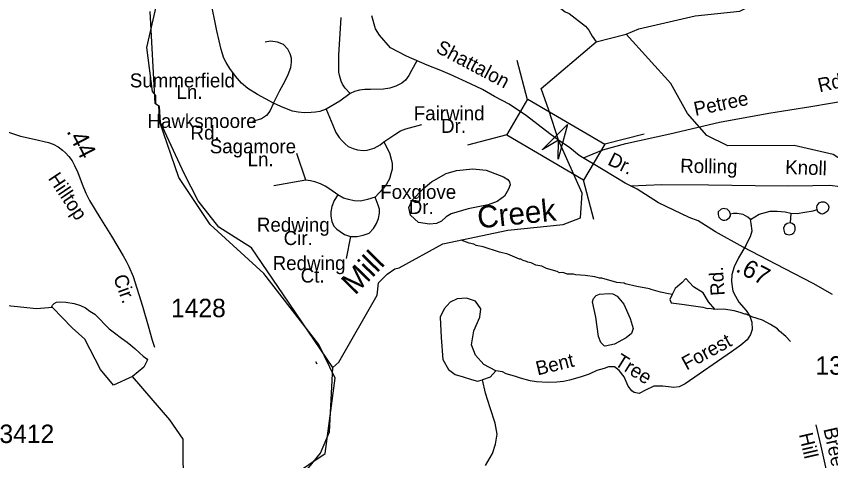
# Model space of a CAD drawing. Extents: x 1547597 to 1699558, y 810033 to 920809.
# Drawn here: x 1600633 to 1606161, y 866479 to 869495 of the extents above; entities that cross this region are included whole.
import ezdxf

# ---------------------------------------------------------------- set-up
doc = ezdxf.new("R2010")
doc.units = 0
for name, color, linetype in [('Exist Boundary Political City Limit New', 7, 'Continuous'), ('Exist Hydrographic Creek Single Shore', 7, 'Continuous'), ('Exist Hydrographic Creek Single Shore Label', 7, 'Continuous'), ('Exist Hydrographic Misc Water Feature', 7, 'Continuous'), ('Exist Road Non-System Type 51', 7, 'Continuous'), ('Exist Road Non-System Type 51 Label', 7, 'Continuous'), ('Exist Road Secondary Mileage Hundredths English Label', 7, 'Continuous'), ('Exist Road Secondary Structure Standard Bridge Attributed CELL', 7, 'Continuous'), ('Exist Road Secondary Structure Standard Bridge CELL', 7, 'Continuous'), ('Exist Road Secondary Type 51 Attributed', 7, 'Continuous'), ('Exist Road Secondary Type 51 Label', 7, 'Continuous'), ('Exist Road Secondary Type 51 Number Label', 7, 'Continuous'), ('Map Preparation Boundary City Limit Buffer Line', 7, 'Continuous')]:
    doc.layers.add(name, color=color, linetype=linetype)

msp = doc.modelspace()

# ---------------------------------------------------------------- linework, layer by layer
at = {"layer": 'Exist Boundary Political City Limit New'}
msp.add_lwpolyline([(1602182.3, 866158.9), (1602728.1, 866528.3), (1602797.7, 867040.1), (1602687, 867268.5), (1602313.6, 867748.7), (1601948.4, 868081.1), (1601736.8, 868400.2), (1601607.9, 868777), (1601600.8, 868885.5), (1601575.9, 868902.4), (1601540.5, 869526.8)], dxfattribs=at)
at = {"layer": 'Exist Hydrographic Creek Single Shore'}
for p, q in [((1602673.7, 867133.8), (1602666.3, 867149.1)), ((1602782, 867111.8), (1602822, 867147))]:
    msp.add_line(p, q, dxfattribs=at)
for points in [[(1602782, 867111.8), (1602446.7, 867604.6), (1602229.1, 867924.7), (1602006.9, 868065), (1601866.6, 868242.5), (1601771.4, 868427.8), (1601611.7, 868773.7), (1601604.6, 868882.2), (1601579.7, 868899.1), (1601580.6, 868958.2), (1601556.6, 868985), (1601518.7, 869284.4), (1601660.7, 869908.5), (1601652.7, 869984.2), (1601436.5, 870359), (1601193.2, 870745.3), (1601139.7, 870848.1), (1601187.9, 871530), (1601203.8, 872030.5)], [(1604772.6, 869373), (1604858.4, 869409.8), (1605241.6, 869498.8), (1605544.1, 869530.6), (1605598.7, 869556.2), (1605619.6, 869874.2), (1605773, 870044.1), (1605865.7, 870145), (1606007.7, 870168.4), (1606156.7, 870139), (1606380.7, 870062.2), (1606464.7, 870086.8), (1606526.7, 870384.3)], [(1602822, 867147), (1603081.4, 867603.2), (1603090.9, 867686.5), (1603150.5, 867745.3), (1603201.6, 867782.2), (1603230.9, 867786.9), (1603526.7, 867950.3), (1603969.7, 868043.1), (1604345.6, 868081.3), (1604462.6, 868128.3), (1604473.7, 868295.4), (1604312.8, 868655.6), (1604247.6, 868858.1), (1604194.2, 869006.1), (1604567.5, 869322.3), (1604772.6, 869373)], [(1609800.9, 867054.7), (1609388.7, 867371.7), (1609141.7, 867616.4), (1608700.6, 868304.8), (1608609.5, 868481.4), (1608545.4, 868703.9), (1608295.7, 868611.8), (1608057.2, 868545.5), (1607826.7, 868417.8), (1607675.7, 868378.1), (1607125.6, 868402.5), (1606741.7, 868331.5), (1606417.7, 868403.8), (1606177.7, 868556.3), (1605911.6, 868617.5), (1605461.6, 868616.8), (1605320.7, 868685.3), (1605189.6, 868835.7), (1605075.6, 869038.3), (1604772.6, 869373)], [(1601757.5, 865749.5), (1601849, 865879.6), (1601967.7, 866038.6), (1602617.6, 866432.8), (1602698.5, 866529.3), (1602757.6, 866675.7), (1602782, 867111.8)]]:
    msp.add_lwpolyline(points, dxfattribs=at)
at = {"layer": 'Exist Hydrographic Misc Water Feature'}
for points in [[(1603836.5, 870023.7), (1603852.9, 869984), (1603860.6, 869967.9), (1603913.3, 869883), (1603976, 869805.9), (1604021.5, 869771.2), (1604041, 869750.9), (1604185.2, 869638.5), (1604274.4, 869586.9), (1604317.9, 869558.2), (1604359.3, 869525.5), (1604385.1, 869513.1), (1604495.6, 869427.2), (1604519.2, 869400.8), (1604540.5, 869360.4), (1604567.5, 869322.3)], [(1603939.2, 868405.8), (1603968.8, 868387.1), (1603980.3, 868372.8), (1603983.8, 868350.7), (1603973.1, 868320.9), (1603946, 868273.6), (1603897.1, 868238.8), (1603834.6, 868216.3), (1603699.8, 868187.5), (1603585, 868154.3), (1603550.5, 868133.2), (1603517.7, 868104), (1603485.4, 868088.7), (1603437.3, 868083.9), (1603363.4, 868095.7), (1603308.7, 868145.1), (1603297.9, 868197.3), (1603319.2, 868246.8), (1603397.2, 868327), (1603450.3, 868371.7), (1603549.7, 868429.2), (1603620.2, 868449.5), (1603730.5, 868460.9), (1603822.3, 868450.6), (1603939.2, 868405.8)], [(1605084.2, 867607.5), (1605060.4, 867611.9), (1605004.6, 867622.8), (1604940.9, 867640), (1604931, 867646.1), (1604845.3, 867661.5), (1604765.6, 867678.8), (1604757.6, 867683), (1604709.7, 867687.8), (1604606.3, 867717.6), (1604590.3, 867717.8), (1604558.5, 867726.4), (1604494.6, 867735.4), (1604430.7, 867740.5), (1604414.9, 867744.7), (1604374.9, 867745.5), (1604343, 867756), (1604319, 867754.4), (1604303.1, 867762.7), (1604231.5, 867783.8), (1604199.8, 867798.4), (1604160, 867807.1), (1604128.2, 867821.5), (1604104.3, 867825.9), (1604096.4, 867832.1), (1604072.5, 867838.5), (1604056.6, 867846.8), (1604048.6, 867847), (1603969.2, 867880.3), (1603913.4, 867893.2), (1603802.1, 867931), (1603754.3, 867939.8), (1603738.4, 867948.1), (1603706.5, 867954.7), (1603651.5, 867975.6)], [(1601422.3, 867051.2), (1601292.4, 866991.2), (1601204.1, 867097.9), (1601097.6, 867304.5), (1601011, 867381.2), (1600878.1, 867519.7), (1600769.5, 867509.6), (1600203.6, 867568), (1599611.6, 867566.9), (1599145.6, 867642), (1598580.6, 867797.8), (1598356.6, 867825.4), (1598147.6, 867796.8), (1597928.6, 867647), (1597853.6, 867625.5), (1597719.6, 867634.8), (1597188.6, 867816.2)], [(1605373.1, 867508.3), (1605331.4, 867557.5), (1605294.1, 867617.5), (1605229.8, 867659.2), (1605177.7, 867715.7), (1605151.7, 867688.7), (1605103.9, 867647.9), (1605084.2, 867607.5)], [(1604656.5, 867614.2), (1604682.4, 867611.6), (1604712.1, 867596.8), (1604756.8, 867541.7), (1604800.4, 867444.7), (1604820.7, 867376.2), (1604807.9, 867342.5), (1604773.2, 867313.3), (1604694.1, 867269.2), (1604629.7, 867256.8), (1604621.8, 867259), (1604600.3, 867281.5), (1604585.3, 867321.9), (1604566.6, 867452.3), (1604543.1, 867556.9), (1604549.7, 867580.8), (1604568.1, 867600.4), (1604591.5, 867609.8), (1604656.5, 867614.2)], [(1605084.2, 867607.5), (1605068.3, 867574), (1605077.9, 867550.6), (1605149.9, 867541), (1605213.3, 867533.2), (1605292.3, 867520.1), (1605323.6, 867512.3), (1605338.3, 867514.1), (1605373.1, 867508.3)], [(1600878.1, 867519.7), (1600874.5, 867525.2), (1600877.6, 867535.1), (1600889.6, 867546.8), (1600904.5, 867554.3), (1600928, 867558), (1600969.4, 867555.6), (1601024.3, 867546), (1601069.3, 867531.7), (1601101.6, 867515.5), (1601132.8, 867494.5), (1601165, 867472.4), (1601199, 867440.5), (1601231, 867405.7), (1601262.2, 867374.8), (1601298.2, 867346.8), (1601346, 867310.8), (1601385.2, 867282.8), (1601410.6, 867262.9), (1601437, 867239.8), (1601467.9, 867211), (1601494.9, 867188.9), (1601519.1, 867170), (1601522.4, 867164.3), (1601497.2, 867112.9), (1601422.3, 867051.2)], [(1605886.7, 867288), (1605855.3, 867322.5), (1605813.9, 867357.3), (1605800.2, 867373.5), (1605752.7, 867404.2), (1605697.1, 867433.2), (1605625.6, 867456.4), (1605585.9, 867473), (1605577.9, 867473.2), (1605546.1, 867485.8), (1605506.2, 867496.4), (1605434.5, 867507.6), (1605394.5, 867506.3), (1605373.1, 867508.3)], [(1601757.5, 865749.5), (1601708.7, 865968.3), (1601768.1, 866270.9), (1601765, 866625.9), (1601674.7, 866756.7), (1601422.3, 867051.2)]]:
    msp.add_lwpolyline(points, dxfattribs=at)
at = {"layer": 'Exist Road Non-System Type 51'}
msp.add_line((1605890.6, 868159), (1605884.8, 868093.9), dxfattribs=at)
for points in [[(1602378.2, 868906.5), (1602270.1, 868964), (1602204, 869004.2), (1602162, 869041.8), (1602121.5, 869089.1), (1602082.5, 869140.3), (1602058, 869180.5), (1602041.2, 869211.7), (1602022.7, 869270), (1602008.9, 869328.8), (1601994.4, 869395.7), (1601950, 869611.2), (1601960.6, 869701.2)], [(1602898.6, 868970.8), (1602864.8, 869008), (1602847.9, 869035), (1602837.7, 869055.3), (1602827.6, 869085.7), (1602820.9, 869116.8), (1602820.9, 869169.9), (1602822.8, 869231.7), (1602837.7, 869488)], [(1604481.7, 868533.9), (1604614.2, 868587.9), (1604771, 868632.3), (1605068.9, 868698.1), (1605405.3, 868777.1), (1605741.6, 868838.3), (1606025.8, 868883), (1606293.4, 868928.8), (1606597.7, 868976.9), (1606748.7, 868992.9), (1606847.1, 869018.1), (1606975.2, 869059.3), (1607101.1, 869116.5), (1607378.7, 869245.9), (1607486.3, 869292.2), (1607650.2, 869338.4), (1607796.1, 869361.4), (1607856, 869368.9), (1607924.6, 869370.1), (1608010.6, 869365.4)], [(1602378.2, 868906.5), (1602422.2, 868991.1), (1602456, 869051.9), (1602479.1, 869100), (1602496.5, 869146.6), (1602501.4, 869184.5), (1602499.9, 869210.8), (1602491.5, 869239.8), (1602475.5, 869271.7), (1602446.7, 869303.5), (1602405.3, 869319), (1602358, 869325.8), (1602320.8, 869319)], [(1603351.3, 869193.9), (1603314.1, 869126.3), (1603297.2, 869092.5), (1603274.6, 869062.1), (1603249.9, 869041.8), (1603209.4, 869021.5), (1603168.9, 869008), (1603124.9, 869001.2), (1603037.1, 868997.8), (1602997.6, 868999.1), (1602962.8, 868994.4), (1602929, 868984.3), (1602898.6, 868970.8)], [(1602898.6, 868970.8), (1602827.6, 868920.1), (1602736.4, 868866)], [(1602378.2, 868906.5), (1602354.6, 868852.4), (1602330.9, 868822), (1602297.2, 868798.4), (1602236.3, 868781.5)], [(1602736.4, 868866), (1602692.5, 868849.1), (1602663.7, 868843.8), (1602634.1, 868842), (1602589.5, 868841), (1602546.9, 868843.8), (1602506.6, 868852.4), (1602466.2, 868867), (1602428.1, 868881.9), (1602378.2, 868906.5)], [(1602736.4, 868866), (1602780.1, 868755.2), (1602800.6, 868707.1), (1602824.2, 868673.3), (1602844.5, 868649.6), (1602864.8, 868629.3), (1602885, 868612.4), (1602918.8, 868598.9), (1602949.2, 868588.7), (1602986.4, 868585.4), (1603014, 868585.8), (1603062.6, 868600.2), (1603102.9, 868623.8), (1603128.3, 868642.8)], [(1603128.3, 868642.8), (1603202.6, 868693.6), (1603239.8, 868717.2), (1603277, 868730.7), (1603385.1, 868761.2)], [(1603128.3, 868642.8), (1603165.5, 868568.5), (1603178.2, 868525.5), (1603184.5, 868496.4), (1603182.9, 868458.6), (1603175.6, 868426.5), (1603165.5, 868392.7), (1603145.2, 868355.5), (1603124.9, 868328.4), (1603094.5, 868294.6), (1603067.5, 868267.6)], [(1602597.9, 868382.5), (1602537, 868565.1)], [(1602597.9, 868382.5), (1602381.6, 868345.3)], [(1602814.1, 868284.5), (1602760, 868321.7), (1602729.6, 868342), (1602697.2, 868358.6), (1602658.7, 868372.4), (1602629.3, 868379.5), (1602597.9, 868382.5)], [(1604802.5, 868344.5), (1605014.2, 868353.8), (1605332.2, 868351.2), (1605647.8, 868346.6), (1605873.7, 868344.6), (1606039.5, 868345.7), (1606155.2, 868350), (1606224.6, 868339.9), (1606265.2, 868317.4), (1606285.3, 868299.4), (1606307, 868271.9), (1606330.1, 868202.4), (1606334.5, 868054.8), (1606354.7, 867821.9), (1606387.7, 867575.2), (1606431.4, 867284)], [(1602814.1, 868284.5), (1602790.7, 868245.8), (1602773.5, 868203.3), (1602767.5, 868168.6), (1602766.8, 868139.1), (1602773.6, 868101.8), (1602787.1, 868071.5), (1602807.3, 868051.2), (1602831, 868034.3), (1602861.4, 868014), (1602901.9, 868000.5)], [(1603067.5, 868267.6), (1603016.8, 868250.7), (1602969.5, 868240.5), (1602926.5, 868242.2), (1602888.4, 868250.7), (1602854.6, 868260.8), (1602814.1, 868284.5)], [(1602901.9, 868000.5), (1602945.9, 868000.5), (1602986.4, 868010.6), (1603026.9, 868024.2), (1603057.4, 868054.6), (1603077.6, 868088.4), (1603091.1, 868122.2), (1603097.9, 868159.4), (1603097.9, 868186.4), (1603087.8, 868213.5), (1603067.5, 868267.6)], [(1605890.6, 868159), (1605934, 868157.6), (1605986, 868164.8), (1606042.4, 868174.9), (1606068.4, 868183.6)], [(1605615.9, 868115.6), (1605598.5, 868133), (1605565.3, 868150.3), (1605524.8, 868156.1), (1605501.7, 868156.1), (1605480, 868153.2)], [(1605615.9, 868115.6), (1605675.2, 868151.8), (1605748.9, 868172.1), (1605798.1, 868173.5), (1605851.6, 868167.7), (1605890.6, 868159)], [(1605584.1, 867939.1), (1605615.9, 867999.9), (1605627.4, 868038.9), (1605621.7, 868089.6), (1605615.9, 868115.6)], [(1602901.9, 868000.5), (1602871.5, 867851.7)], [(1605584.1, 867939.1), (1605534.9, 867856.6), (1605504.5, 867794.4), (1605488.6, 867742.3), (1605486.3, 867696.3), (1605491.5, 867661.5), (1605496.6, 867629.3), (1605514.6, 867595.8), (1605537.8, 867554.6), (1605586.8, 867497.9), (1605610.9, 867460.3), (1605625.8, 867419.4), (1605628, 867369), (1605615.1, 867335.5), (1605594.5, 867299.4), (1605550.7, 867263.3), (1605486.3, 867217), (1605173.4, 867000.7), (1605132.1, 866980.9), (1605093.2, 866976.4), (1605077.8, 866978.9), (1605021.1, 866984.1), (1604985.1, 866984.1), (1604960.5, 866985.1), (1604903, 866957.2), (1604861.4, 866935.1), (1604826.4, 866941.5), (1604811.5, 866952.6), (1604786.8, 866984.1), (1604758.4, 867048.5), (1604725, 867092.3), (1604694.1, 867115.5), (1604652.8, 867115.5), (1604621.9, 867105.2), (1604573, 867092.3), (1604521.5, 867066.6), (1604459.7, 867045.9), (1604387.6, 867025.3), (1604347.2, 867016.6), (1604302.6, 867012.9), (1604238.2, 867009.9), (1604163.5, 867015), (1604119.8, 867020.2), (1604055.4, 867038.2), (1604014.2, 867053.7), (1603957.5, 867069.1), (1603931.8, 867082), (1603888, 867089.8)], [(1603888, 867089.8), (1603805.1, 867131.7), (1603749, 867195.4), (1603722.8, 867266.5), (1603737.8, 867360.1), (1603778.9, 867453.7), (1603786.4, 867509.9), (1603749, 867562.3), (1603689.2, 867581), (1603625.6, 867577.3), (1603576.9, 867554.8), (1603535.8, 867509.9), (1603509.6, 867453.7), (1603517.1, 867315.2), (1603528.3, 867165.4), (1603565.7, 867098), (1603610.6, 867064.3), (1603666.7, 867049.3), (1603722.8, 867030.6), (1603764, 867019.4), (1603797.9, 867027.9)], [(1603888, 867089.8), (1603850, 867045.6), (1603797.9, 867027.9)], [(1603818.5, 866445.4), (1603864.8, 866527.9), (1603885.4, 866592.3), (1603895.7, 866659.3), (1603882.8, 866734.1), (1603849.4, 866837.2), (1603818.5, 866937.7), (1603797.9, 867027.9)], [(1606180.6, 866197.7), (1606151, 866333.7), (1606095.6, 866578.5), (1606062.3, 866723.1)]]:
    msp.add_lwpolyline(points, dxfattribs=at)
for points in [[(1606068.4, 868183.6), (1606067, 868196.7), (1606068.4, 868211.1), (1606081.5, 868229.9), (1606098.8, 868235.7), (1606116.2, 868235.7), (1606130.6, 868228.5), (1606142.2, 868215.5), (1606148, 868199.5), (1606145.1, 868188), (1606140.7, 868174.9), (1606130.6, 868166.3), (1606116.2, 868156.1), (1606103.1, 868153.2), (1606094.5, 868154.7), (1606081.5, 868160.5), (1606074.2, 868167.7)], [(1605480, 868153.2), (1605474.2, 868169.2), (1605456.8, 868186.5), (1605442.4, 868189.4), (1605432.2, 868190.9), (1605416.3, 868185.1), (1605397.5, 868167.7), (1605396.1, 868148.9), (1605401.9, 868131.5), (1605414.9, 868118.5), (1605427.9, 868111.3), (1605440.9, 868111.3), (1605452.5, 868114.2), (1605462.6, 868120), (1605472.7, 868130.1), (1605481.4, 868140.2)], [(1605884.8, 868093.9), (1605864.6, 868089.6), (1605850.1, 868076.5), (1605840, 868057.7), (1605841.4, 868043.3), (1605847.2, 868025.9), (1605858.8, 868015.8), (1605880.5, 868011.4), (1605896.4, 868015.8), (1605909.4, 868025.9), (1605919.5, 868043.3), (1605919.5, 868065), (1605913.7, 868078), (1605899.3, 868089.6)]]:
    msp.add_lwpolyline(points, close=True, dxfattribs=at)
at = {"layer": 'Exist Road Secondary Structure Standard Bridge Attributed CELL'}
msp.add_lwpolyline([(1604201, 868589.4), (1604374.4, 868760.9), (1604309.9, 868525.7), (1604312.8, 868655.6)], close=True, dxfattribs=at)
at = {"layer": 'Exist Road Secondary Structure Standard Bridge CELL'}
for p, q in [((1604102.6, 868927.8), (1604033.1, 869194.9)), ((1603963, 868689.8), (1603695.9, 868620.2)), ((1604893.6, 868695.9), (1604626.5, 868626.3)), ((1604553.2, 868115.7), (1604483.6, 868382.8))]:
    msp.add_line(p, q, dxfattribs=at)
msp.add_lwpolyline([(1604483.6, 868382.8), (1603962.3, 868688.7), (1604105.2, 868932.2), (1604626.5, 868626.3)], close=True, dxfattribs=at)
at = {"layer": 'Exist Road Secondary Type 51 Attributed'}
for points in [[(1604312.8, 868655.6), (1604254.5, 868697.6), (1604095.6, 868819.5), (1603978.1, 868899), (1603879.3, 868951.5), (1603797.6, 868999.3), (1603715.8, 869037.9), (1603578.5, 869101.2), (1603513.7, 869127.5), (1603421.7, 869164.5), (1603280.2, 869223.6), (1603172.8, 869281.8), (1603097.2, 869366.7), (1603071, 869409.9), (1603046.3, 869497.9)], [(1600558.6, 868714.9), (1600662.1, 868682.3), (1600753, 868662), (1600852, 868637.6), (1600881.9, 868626.2), (1600916.7, 868608.1), (1600946.2, 868587.4), (1600966.9, 868569.3), (1600990.3, 868543.6), (1601012.3, 868513.6), (1601028.2, 868483.2), (1601049.3, 868434.6), (1601080.1, 868356.1), (1601105.3, 868294.3), (1601129, 868245.8), (1601198.9, 868128.5), (1601278.4, 868003.5), (1601359, 867869.4), (1601379.2, 867832.9), (1601397.3, 867797.6), (1601425, 867728.7), (1601489.8, 867526.9), (1601528.1, 867393.9), (1601554.5, 867296.8), (1601570.8, 867248.6)], [(1606171.7, 867607.4), (1606041.6, 867681.8), (1605848.1, 867782.3), (1605565.4, 867927.5), (1605379.4, 868031.7), (1605260.4, 868106.1), (1605200.8, 868128.5), (1604992.5, 868229), (1604847.4, 868322), (1604765.6, 868363), (1604616.8, 868452.3), (1604453.5, 868550.9), (1604390.3, 868603.4), (1604312.8, 868655.6)]]:
    msp.add_lwpolyline(points, dxfattribs=at)
at = {"layer": 'Map Preparation Boundary City Limit Buffer Line'}
msp.add_lwpolyline([(1602182.3, 866158.9), (1602728.1, 866528.3), (1602797.7, 867040.1), (1602687, 867268.5), (1602313.6, 867748.7), (1601948.4, 868081.1), (1601736.8, 868400.2), (1601607.9, 868777), (1601600.8, 868885.5), (1601575.9, 868902.4), (1601540.5, 869526.8)], dxfattribs=at)

# ---------------------------------------------------------------- texts
at = {"layer": 'Exist Hydrographic Creek Single Shore Label'}
for s, rotation, p in [('Creek', 5.808, (1603769.7, 868055)), ('Mill', 45.5262, (1602931.4, 867598.2))]:
    msp.add_text(s, height=150, rotation=rotation, dxfattribs=at).set_placement(p)
at = {"layer": 'Exist Road Non-System Type 51 Label'}
for s, p in [('Summerfield', (1601403.4, 869012.6)), ('Ln.', (1601720.2, 868934.6)), ('Fairwind', (1603330.7, 868789.8)), ('Hawksmoore', (1601523, 868737.2)), ('Dr.', (1603515.7, 868703.9)), ('Rd.', (1601815.2, 868658.1)), ('Sagamore', (1601945.7, 868565.2)), ('Ln.', (1602202.7, 868477)), ('Foxglove', (1603103.1, 868256.1)), ('Dr.', (1603296.2, 868153)), ('Redwing', (1602265.8, 868033.3)), ('Cir.', (1602447.5, 867942.8)), ('Redwing', (1602372.8, 867772.9)), ('Ct.', (1602562.6, 867688.1))]:
    msp.add_text(s, height=95, dxfattribs=at).set_placement(p)
for s, rotation, p in [('Rd.', 12.9036, (1606085.2, 868978.5)), ('Petree', 11.789, (1605242, 868818.7)), ('Rolling', 359.1634, (1605138.5, 868433.3)), ('Knoll', 358.1445, (1605850.4, 868425.1)), ('Rd.', 93.6142, (1605441.1, 867601.6)), ('Forest', 28.6979, (1605182.2, 867090.4)), ('Bent', 13.7592, (1604171.9, 867057.3)), ('Tree', 327.9451, (1604687.1, 867131.4)), ('Breeze', 282.763, (1606110.2, 866694)), ('Hill', 282.9666, (1605944.3, 866657.8))]:
    msp.add_text(s, height=95, rotation=rotation, dxfattribs=at).set_placement(p)
at = {"layer": 'Exist Road Secondary Mileage Hundredths English Label'}
for s, rotation, p in [('.44', 297.411, (1600971.2, 868715.4)), ('.67', 332.8207, (1605509.4, 867766))]:
    msp.add_text(s, height=120, rotation=rotation, dxfattribs=at).set_placement(p)
at = {"layer": 'Exist Road Secondary Type 51 Label'}
for s, rotation, p in [('Shattalon', 332.0229, (1603474.1, 869255)), ('Dr.', 333.8077, (1604640.4, 868491.6)), ('Hilltop', 303.7323, (1600844.9, 868395.2)), ('Cir.', 290.0206, (1601289.3, 867723.5))]:
    msp.add_text(s, height=95, rotation=rotation, dxfattribs=at).set_placement(p)
at = {"layer": 'Exist Road Secondary Type 51 Number Label'}
for s, p in [('1428', (1601682.6, 867453)), ('1393', (1606057.1, 867062.7)), ('3412', (1600518.3, 866599.1))]:
    msp.add_text(s, height=125, dxfattribs=at).set_placement(p)

doc.saveas('drawing.dxf')
